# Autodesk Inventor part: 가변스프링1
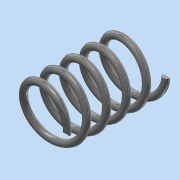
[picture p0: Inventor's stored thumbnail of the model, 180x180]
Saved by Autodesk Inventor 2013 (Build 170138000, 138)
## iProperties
Created: 2018-10
Part Number: 가변스프링1
Material: 스테인리스강
Document SubType Name: Modeling
Designer: Administrator
Density: 8.08 g/cm^3
Mass: 6.30638 g
Surface Area: 15.7949 cm^2
Volume: 0.780493 cm^3
Author: Administrator
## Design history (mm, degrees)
sketch "스케치1"
  geometry: L1 (0, 0)-(0, 30.256); L2 (0, 0)-(8, 0); L3 (0, 30.256)-(8, 30.256); C1 r 1 at (8, 0)
  constraints: 6 end point, 1 centre point, 1 coincident, 1 parallel, 1 perpendicular, 1 vertical
  dimensions: "d0" = 30.25555 distance of L1.start L1.end (derived); "d3" = 8 distance of L1.start L2.end; "d4" = 2 diameter of C1; "d5" = 8 distance of L1.end L3.end
feature "코일1" sketch "스케치1" pitch "d6" = 10; turns "d8" = 5; dims "d7" = 30.25555 (= d0), "d9" = 0, angle "d10" = 90 deg, angle "d11" = 90 deg, "d12" = 0, "d13" = 0
sketch "스케치2"
  geometry: L1 (30.256, 10)-(0, 10); L2 (0, 10)-(0, -10); L3 (0, -10)-(30.256, -10); L4 (30.256, -10)-(30.256, 10); 2 further points
  constraints: 8 end point, 2 parallel, 1 coincident, 1 horizontal, 1 midpoint, 1 perpendicular
  dimensions: "d14" = 30.25555 distance of L2.end L3.end (derived); "d16" = 20 distance of L3.end L1.start
extrude "돌출1" sketch "스케치2" stored distance "d17" = 0; taper "d18" = 0 deg
node "솔리드1"
